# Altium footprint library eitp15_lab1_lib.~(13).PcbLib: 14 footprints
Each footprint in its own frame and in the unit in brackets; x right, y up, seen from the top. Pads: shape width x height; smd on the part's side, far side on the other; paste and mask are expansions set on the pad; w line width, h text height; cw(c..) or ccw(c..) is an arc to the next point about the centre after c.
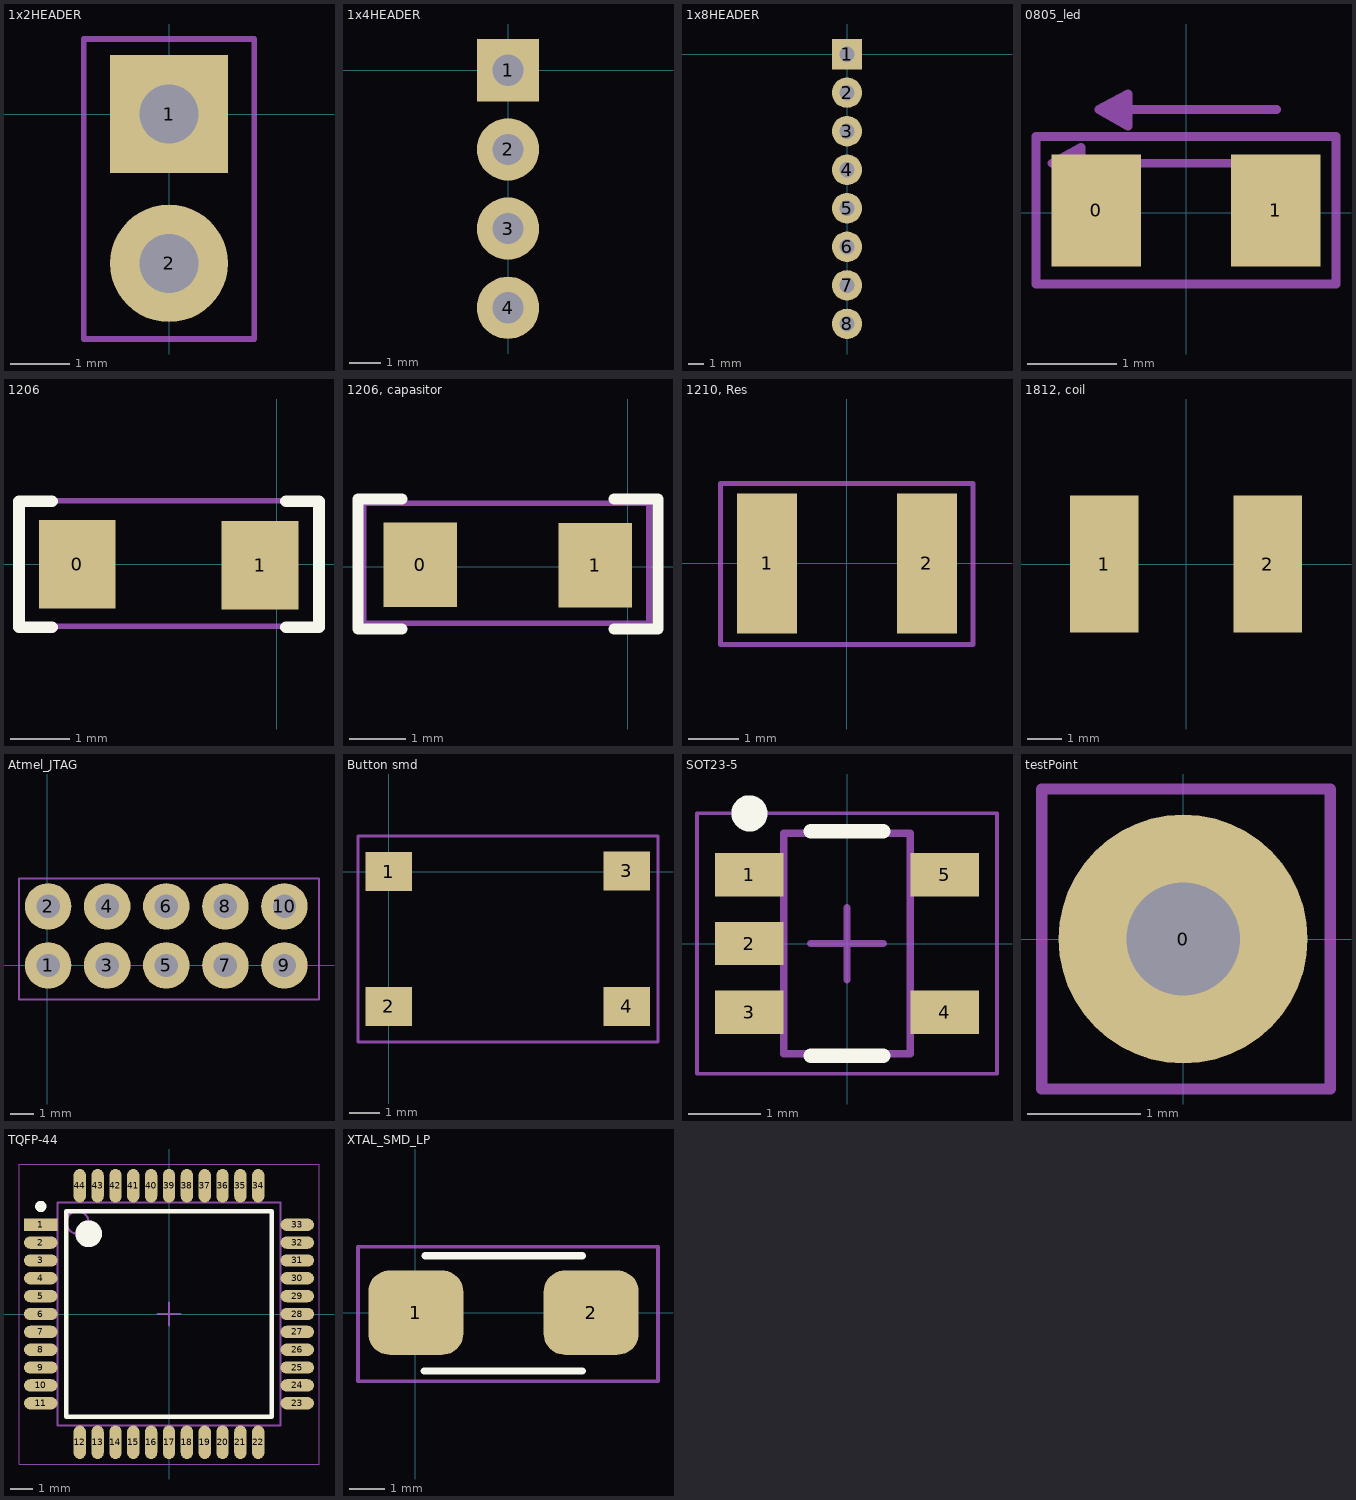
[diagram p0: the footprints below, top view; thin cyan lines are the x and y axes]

## 1x2HEADER [mm] "Pad Diameter 2 mm, Hole  1 mm, Pitch 2.54 mm"
pads (2):
  rect 2x2 hole 1: 1(0,0)
  round 2 hole 1: 2(0,-2.54)
Mechanical 13:
  lines w0.1: -1.45,-3.825 1.45,-3.825 1.45,1.275 -1.45,1.275 -1.45,-3.825
  text ".Designator" at 0.35,-3.275 h1
3D body "User Library-Header Vertical 2_54mm Pitch2-1.STEP": height 5.94, standoff -2.94, extent -1.27,-1.27 1.27,1.27
3D body "User Library-Header Vertical 2_54mm Pitch2-1.STEP": height 5.94, standoff -2.94, extent -1.27,-3.81 1.27,-1.27

## 1x4HEADER [mm] "Pad Diameter 2 mm, Hole  1 mm, Pitch 2.54 mm"
pads (4):
  rect 2x2 hole 1: 1(0,0)
  round 2 hole 1: 2(0,-2.54) 3(0,-5.08) 4(0,-7.62)
3D body "User Library-Header Vertical 2_54mm Pitch2-1.STEP": height 5.94, standoff -2.94, extent -1.27,-8.89 1.27,-6.35
3D body "User Library-Header Vertical 2_54mm Pitch2-1.STEP": height 5.94, standoff -2.94, extent -1.27,-6.35 1.27,-3.81
3D body "User Library-Header Vertical 2_54mm Pitch2-1.STEP": height 5.94, standoff -2.94, extent -1.27,-1.27 1.27,1.27
3D body "User Library-Header Vertical 2_54mm Pitch2-1.STEP": height 5.94, standoff -2.94, extent -1.27,-3.81 1.27,-1.27

## 1x8HEADER [mm] "Pad Diameter 2 mm, Hole  1 mm, Pitch 2.54 mm"
pads (8):
  rect 2x2 hole 1: 1(0,0)
  round 2 hole 1: 2(0,-2.54) 3(0,-5.08) 4(0,-7.62) 5(0,-10.16) 6(0,-12.7) 7(0,-15.24) 8(0,-17.78)
3D body "User Library-Header Vertical 2_54mm Pitch2-1.STEP": height 5.94, standoff -2.94, extent -1.27,-1.27 1.27,1.27
3D body "User Library-Header Vertical 2_54mm Pitch2-1.STEP": height 5.94, standoff -2.94, extent -1.27,-3.81 1.27,-1.27
3D body "User Library-Header Vertical 2_54mm Pitch2-1.STEP": height 5.94, standoff -2.94, extent -1.27,-6.35 1.27,-3.81
3D body "User Library-Header Vertical 2_54mm Pitch2-1.STEP": height 5.94, standoff -2.94, extent -1.27,-8.89 1.27,-6.35
3D body "User Library-Header Vertical 2_54mm Pitch2-1.STEP": height 5.94, standoff -2.94, extent -1.27,-11.43 1.27,-8.89
3D body "User Library-Header Vertical 2_54mm Pitch2-1.STEP": height 5.94, standoff -2.94, extent -1.27,-13.97 1.27,-11.43
3D body "User Library-Header Vertical 2_54mm Pitch2-1.STEP": height 5.94, standoff -2.94, extent -1.27,-16.51 1.27,-13.97
3D body "User Library-Header Vertical 2_54mm Pitch2-1.STEP": height 5.94, standoff -2.94, extent -1.27,-19.05 1.27,-16.51

## 0805_led [mm]
pads (2):
  rect 1x1.25 smd: 0(-1,0.025) 1(1,0.025)
Mechanical 13:
  lines w0.1: 0.485,0.55 -1.498,0.55 ; 1.01,1.15 -0.972,1.15 ; -1.498,0.55 -1.175,0.725 ; -1.498,0.55 -1.175,0.367 ; -1.175,0.367 -1.175,0.725 ; -1.175,0.367 -1.282,0.55 -1.175,0.725 ; -0.972,1.15 -0.65,0.968 ; -0.972,1.15 -0.65,1.325 ; -0.65,0.968 -0.757,1.15 -0.65,1.325 ; -0.65,0.968 -0.65,1.325 ; -1.675,-0.8 -1.675,0.85 1.675,0.85 1.675,-0.8 -1.675,-0.8
  text ".Designator" at -1.425,-0.65 h0.4
3D body "User Library-led_0805.STEP": height 1.1, standoff 0, extent -1.035,-0.6 0.985,0.65

## 1206 [mm] "Generic 1206"
pads (2):
  rect 1.3x1.5 smd: 0(-3.384,-0.003) 1(-0.286,-0.014)
Top Overlay:
  lines w0.2: -3.81,-1.067 -4.369,-1.067 -4.369,1.067 -3.81,1.067 ; 0.152,-1.067 0.711,-1.067 0.711,1.067 0.152,1.067
Mechanical 13:
  lines w0.1: -4.35,-1.05 0.7,-1.05 0.7,1.075 -4.35,1.075 -4.35,-1.05
  text ".Designator" at -3.6,-0.425 h1
3D body "User Library-R_1206.STEP": height -0.4, standoff -1, extent -3.465,-0.793 -0.265,0.807

## 1206, capasitor [mm] "Generic 1206"
pads (2):
  rect 1.3x1.5 smd: 0(-3.673,0.038) 1(-0.575,0.026)
Top Overlay:
  lines w0.2: -4,-1.1 -4.775,-1.1 -4.775,-1 -4.775,-0.767 -4.775,0.843 -4.775,1.2 -4,1.2 ; -0.242,-1.1 0.533,-1.1 0.533,1.2 -0.242,1.2
Mechanical 13:
  lines w0.1: -4.675,-1 -4.675,1.125 0.375,1.125 0.375,-1 -4.675,-1
  text ".Designator" at -3.925,-0.375 h1
3D body "User Library-cap_1206_0_95.STEP": height -0.55, standoff -1.5, extent -3.776,-0.786 -0.576,0.814

## 1210, Res [mm]
pads (2):
  rect 1.2x2.8 smd: 1(-1.6,0) 2(1.6,0)
Mechanical 13:
  lines w0.1: -2.525,-1.625 -2.525,1.6 2.525,1.6 2.525,-1.625 -2.525,-1.625
  text ".Designator" at -1.775,-0.375 h1
3D body "R_1210.STEP": height 0.6, standoff 0, extent -1.6,-1.25 1.6,1.25

## 1812, coil [mm]
pads (2):
  rect 2x4 smd: 1(-2.385,0) 2(2.385,0)
3D body "cap_1812.step": height 2.6, standoff 0, extent -2.3,-1.6 2.3,1.6

## Atmel_JTAG [mm]
pads (10):
  round 2 hole 1: 1(0.028,-0.01) 2(0.028,2.53) 3(2.568,-0.01) 4(2.568,2.53) 5(5.108,-0.01) 6(5.108,2.53) 7(7.648,-0.01) 8(7.648,2.53) 9(10.188,-0.01) 10(10.188,2.53)
Mechanical 13:
  lines w0.1: -1.225,-1.475 -1.225,3.725 11.675,3.725 11.675,-1.475 -1.225,-1.475
  text ".Designator" at -0.35,0.925 h1
3D body "12539.stp": height 8.6, standoff -3.2, extent -1.147,-1.36 11.553,3.64

## Button smd [mm]
pads (4):
  rect 1.55x1.3 smd: 1(0,0) 2(0,-4.5) 3(7.95,0.023) 4(7.95,-4.5)
Mechanical 13:
  lines w0.1: -1.025,-5.7 -1.025,1.2 9,1.2 9,-5.7 -1.025,-5.7
  text ".Designator" at 0.325,-2.475 h1
3D body "User Library-PTS645SL43SMTR92-LFS.STEP": height 4.3, standoff 0, extent -0.55,-5.25 8.45,0.75

## SOT23-5 [mm] "SOT23, 5-Leads, Body 2,90x2,80mm, Pitch 0,95mm, IPC Medium Density"
height 1.1
pads (5):
  rect 0.95x0.6 smd: 1(-1.35,0.95) 2(-1.35,0) 3(-1.35,-0.95) 4(1.35,-0.95) 5(1.35,0.95)
Top Overlay:
  circle w0.25: c-1.35,1.8 r0.125
  lines w0.2: -0.5,-1.55 0.5,-1.55 ; -0.5,1.55 0.5,1.55
Mechanical 13:
  lines w0.1: -0.875,-1.525 0.875,-1.525 0.875,1.525 -0.875,1.525 -0.875,-1.525
Mechanical 15:
  lines w0.05: -2.075,-1.8 2.075,-1.8 2.075,1.8 -2.075,1.8 -2.075,-1.8
  lines w0.1: -0.5,0 0.5,0 ; 0,-0.5 0,0.5
3D body "SW3DPS-SOT-23-5-DEFAULT.STEP": height 1.1, standoff 0, extent -1.25,-1.5 1.25,1.5

## testPoint [mm] "Diameter 2mm, Hole 0.3mm"
pads (1):
  round 2.2 hole 1: 0(0,0)
Mechanical 13:
  lines w0.1: -1.25,-1.325 1.3,-1.325 1.3,1.325 -1.25,1.325 -1.25,-1.325
  text ".Designator" at -1.075,-0.525 h0.4
3D body "User Library-TEST POINT.STEP": height 4.36, standoff -2.57, extent -1.27,-1.315 1.27,1.318

## TQFP-44 [mm] "QFP, 44-Leads, Body 10,00x10,00mm, Pitch 0,80mm, IPC Medium Density"
height 2.45
pads (44):
  rect 1.5x0.55 smd: 1(-5.75,4)
  oval 1.5x0.55 smd: 2(-5.75,3.2) 3(-5.75,2.4) 4(-5.75,1.6) 5(-5.75,0.8) 6(-5.75,0) 7(-5.75,-0.8) 8(-5.75,-1.6) 9(-5.75,-2.4) 10(-5.75,-3.2) 11(-5.75,-4) 23(5.75,-4) 24(5.75,-3.2) 25(5.75,-2.4) 26(5.75,-1.6) 27(5.75,-0.8) 28(5.75,0) 29(5.75,0.8) 30(5.75,1.6) 31(5.75,2.4) 32(5.75,3.2) 33(5.75,4)
  oval 0.55x1.5 smd: 12(-4,-5.75) 13(-3.2,-5.75) 14(-2.4,-5.75) 15(-1.6,-5.75) 16(-0.8,-5.75) 17(0,-5.75) 18(0.8,-5.75) 19(1.6,-5.75) 20(2.4,-5.75) 21(3.2,-5.75) 22(4,-5.75) 34(4,5.75) 35(3.2,5.75) 36(2.4,5.75) 37(1.6,5.75) 38(0.8,5.75) 39(0,5.75) 40(-0.8,5.75) 41(-1.6,5.75) 42(-2.4,5.75) 43(-3.2,5.75) 44(-4,5.75)
Top Overlay:
  circle w0.25: c-5.75,4.825 r0.125
  circle w0.6: c-3.6,3.6 r0.3
  lines w0.2: -4.6,-4.6 -4.6,4.6 4.6,4.6 4.6,-4.6 -4.6,-4.6
Mechanical 13:
  circle w0.1: c-4.1,4.1 r0.5
  lines w0.1: -5,-5 -5,5 5,5 5,-5 -5,-5
Mechanical 15:
  lines w0.05: -6.725,-6.725 -6.725,6.725 6.725,6.725 6.725,-6.725 -6.725,-6.725
  lines w0.1: -0.5,0 0.5,0 ; 0,-0.5 0,0.5
3D body "User Library-TQFP-44-1.STEP": height 1.1, standoff 0, extent -6,-6 6,6

## XTAL_SMD_LP [mm] "Pad 1.7x2.4, Pitch 3.7"
pads (2):
  rrect50% 2.7x2.4 smd: 1(0.02,0) 2(5,0)
Top Overlay:
  lines w0.2: 0.255,-1.657 4.755,-1.657 ; 0.28,1.617 4.755,1.617
Mechanical 13:
  lines w0.1: -1.625,-1.95 -1.625,1.875 6.9,1.875 6.9,-1.95 -1.625,-1.95
  text ".Designator" at -1.175,-0.675 h1
3D body "User Library-445-CRYTAL-SMD.STEP": height 1.35, standoff 0, extent 0.02,-1.6 5.02,1.6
